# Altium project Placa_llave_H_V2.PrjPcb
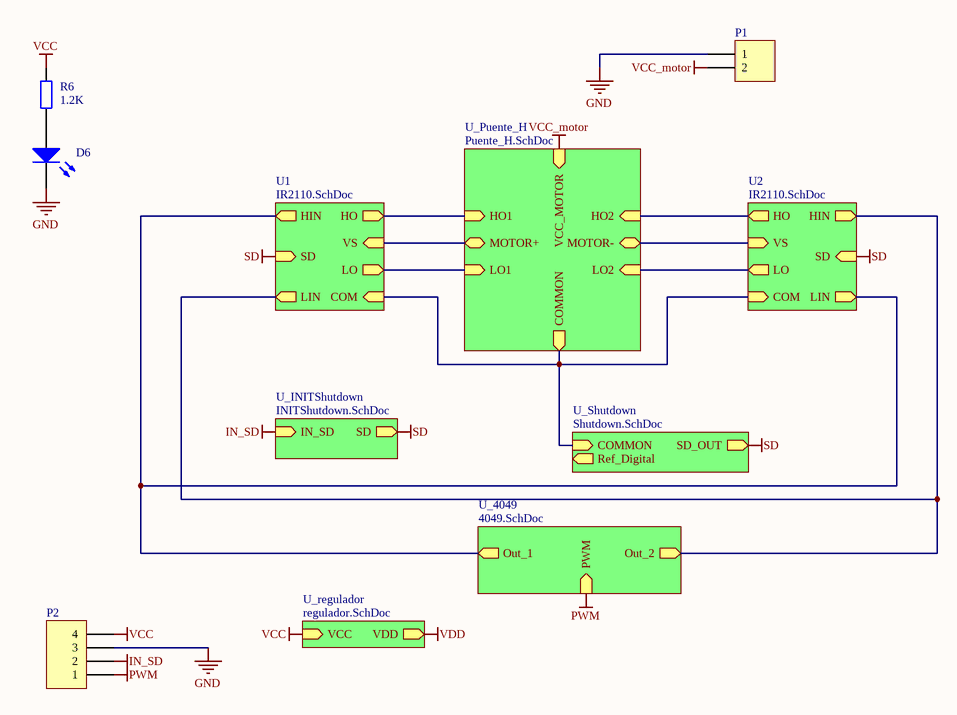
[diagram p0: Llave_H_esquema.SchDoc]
8 sheets, 113 parts. Net scope: hierarchical (ports join the sheet entries above them; power ports are global).
Board file: PCB_llave_H_version_2.PcbDoc
Sheets:
  Llave_H_esquema.SchDoc
    U1 = IR2110.SchDoc
    U2 = IR2110.SchDoc
    U_Puente_H = Puente_H.SchDoc
    U_INITShutdown = INITShutdown.SchDoc
    U_Shutdown = Shutdown.SchDoc
    U_4049 = 4049.SchDoc
    U_regulador = regulador.SchDoc
  ESQUEMA_GRAL.SchDoc

## Sheet Llave_H_esquema.SchDoc
size A4

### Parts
(Parts that share a designator on the sheet are numbered #1, #2 ... from top to bottom, then left to right.)
D6#1  LED0  [CAPPR2.5-6.3X5]  (value not drawn)
P1#1  Header 2  [pwheader1x2]  (value not drawn)
P2#1  Header 4  [HDR1X5]  (value not drawn)
R6#1  1.2k  [AXIAL-0.3]

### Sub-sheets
U1 = IR2110.SchDoc: SD (in), HIN (out), LIN (out), HO (out), LO (out), VS (in), COM (in)
U2 = IR2110.SchDoc: SD (in), HIN (out), LIN (out), HO (out), LO (out), VS (in), COM (in)
U_4049 = 4049.SchDoc: PWM (in), Out_1 (out), Out_2 (out)
U_INITShutdown = INITShutdown.SchDoc: IN_SD (in), SD (out)
U_Puente_H = Puente_H.SchDoc: HO1 (in), LO1 (in), HO2 (in), LO2 (in), MOTOR+ (bidir), MOTOR- (bidir), VCC_MOTOR (in), COMMON (out)
U_regulador = regulador.SchDoc: VCC (in), VDD (out)
U_Shutdown = Shutdown.SchDoc: COMMON (in), SD_OUT (out), Ref_Digital (out)

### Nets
COM: sheet U1/COM, sheet U2/COM, sheet U_Puente_H/COMMON, sheet U_Shutdown/COMMON
GND: D6#1.2(K) P1#1.1 P2#1.3
HIN: sheet U1/HIN, sheet U1/LIN, sheet U2/HIN, sheet U2/LIN, sheet U_4049/Out_1, sheet U_4049/Out_2
HO: sheet U1/HO, sheet U2/HO, sheet U_Puente_H/HO1, sheet U_Puente_H/HO2
IN_SD: P2#1.2 ; sheet U_INITShutdown/IN_SD
LO: sheet U1/LO, sheet U2/LO, sheet U_Puente_H/LO1, sheet U_Puente_H/LO2
MOTOR+: sheet U1/VS, sheet U_Puente_H/MOTOR+
MOTOR-: sheet U2/VS, sheet U_Puente_H/MOTOR-
PWM: P2#1.1 ; sheet U_4049/PWM
SD: sheet U1/SD, sheet U2/SD, sheet U_INITShutdown/SD, sheet U_Shutdown/SD_OUT
VCC: P2#1.4 R6#1.2 ; sheet U_regulador/VCC
VCC_motor: P1#1.2 ; sheet U_Puente_H/VCC_MOTOR
NetD6#1_1: D6#1.1(A) R6#1.1

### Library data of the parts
D6#1 = LED0: Typical INFRARED GaAs LED
P1#1 = Header 2: Header, 2-Pin; value: pw1x2
P2#1 = Header 4: Header, 4-Pin; value: hdr1x5
R6#1 = Res2: Resistor

## Sheet IR2110.SchDoc
size A4
Used 2 times, as channels U1, U2. Parts and nets are listed once, with the designators drawn on the sheet.
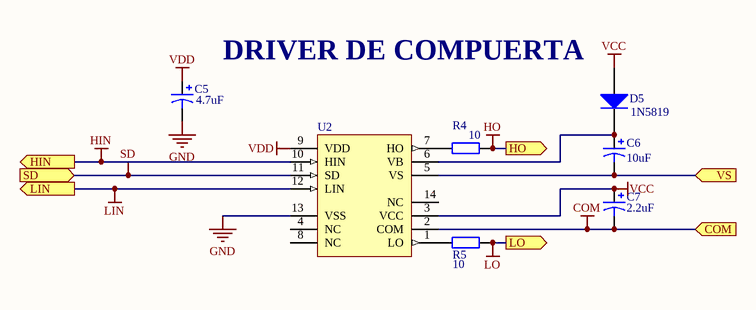
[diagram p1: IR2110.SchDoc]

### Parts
C5  value 4.7uF  [CAPPR2.5-6.3X5]  (hidden comment: Cap Pol1 4.7u)
C6  value 10uF  [CAPPR2.5-6.3X5]  (hidden comment: Cap Pol1)
C7  value 2.2uF  [CAPPR2.5-6.3X5]  (hidden comment: Cap Pol1)
D5  value 1N5819  [DO-204AL]  (hidden comment: Diode)
R4  10  [AXIAL-0.3]
R5  10  [AXIAL-0.3]
U2  IR2110  [PDIP14]  (value not drawn)

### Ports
COM (in), HIN (out), HO (out), LIN (out), LO (out), SD (in), VS (in)

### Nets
COM: C7.2 U2.2(COM) ; port COM
GND: C5.2 U2.13(VSS)
HIN: U2.10(HIN) ; port HIN
HO: R4.2 ; port HO
LIN: U2.12(LIN) ; port LIN
LO: R5.2 ; port LO
SD: U2.11(SD) ; port SD
VCC: C7.1 D5.1(A) U2.3(VCC)
VDD: C5.1 U2.9(VDD)
VS: C6.2 U2.5(VS) ; port VS
NetC6_1: C6.1 D5.2(K) U2.6(VB)
NetR4_1: R4.1 U2.7(HO)
NetR5_1: R5.1 U2.1(LO)

Not connected (* = marked no-connect by the designer): U2 4(NC) 8(NC) 14(NC)

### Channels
U1: designators C5=U1.C5 C6=U1.C6 C7=U1.C7 D5=U1.D5 R4=U1.R4 R5=U1.R5 U2=U1.U2; ports COM=COM HIN=HIN HO=HO LIN=HIN LO=LO SD=SD VS=MOTOR+
U2: designators C5=U2.C5 C6=U2.C6 C7=U2.C7 D5=U2.D5 R4=U2.R4 R5=U2.R5 U2=U2.U2; ports COM=COM HIN=HIN HO=HO LIN=HIN LO=LO SD=SD VS=MOTOR-

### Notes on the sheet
- (near C5) DRIVER DE COMPUERTA

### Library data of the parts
C5-C7 = Cap Pol1: Polarized Capacitor (Radial)
D5 = Diode: 1N5819
R4 R5 = Res2: Resistor
U2 = IR2110: High and Low Side Driver; Note: Pins 4, 8 and 14 are not connected

## Sheet Puente_H.SchDoc
size A4
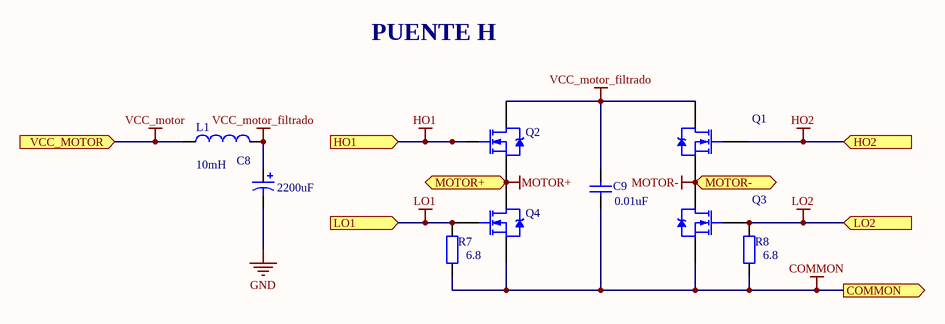
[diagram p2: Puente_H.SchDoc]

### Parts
(Parts that share a designator on the sheet are numbered #1, #2 ... from top to bottom, then left to right.)
C8#1  value 2200uF  [CAPPR5-13X16]  (hidden comment: Cap Pol1)
C9#1  value 0.01uF  [RAD-0.2]  (hidden comment: Cap)
L1#1  value 10mH  [bobina_Choque]  (hidden comment: Inductor)
Q1#1  IRF3205  [To_220_H]  (value not drawn)
Q2#1  IRF3205  [To_220_H]  (value not drawn)
Q3#1  IRF3205  [To_220_H]  (value not drawn)
Q4#1  IRF3205  [To_220_H]  (value not drawn)
R7#1  6.8  [AXIAL-0.3]
R8#1  6.8  [AXIAL-0.3]

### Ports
COMMON (out), HO1 (in), HO2 (in), LO1 (in), LO2 (in), MOTOR+ (bidir), MOTOR- (bidir), VCC_MOTOR (in)

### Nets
COMMON: C9#1.1 Q3#1.3(S) Q4#1.3(S) R7#1.1 R8#1.1 ; port COMMON  [project net COM]
GND: C8#1.2
HO1: Q1#1.1(G) Q2#1.1(G) ; port HO1, port HO2  [also labelled HO2]  [project net HO]
LO1: Q3#1.1(G) Q4#1.1(G) R7#1.2 R8#1.2 ; port LO1, port LO2  [also labelled LO2]  [project net LO]
MOTOR+: Q2#1.3(S) Q4#1.2(D) ; port MOTOR+
MOTOR-: Q1#1.3(S) Q3#1.2(D) ; port MOTOR-
VCC_motor: L1#1.1 ; port VCC_MOTOR
VCC_motor_filtrado: C8#1.1 C9#1.2 L1#1.2 Q1#1.2(D) Q2#1.2(D)

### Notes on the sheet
- PUENTE H

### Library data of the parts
C8#1 = Cap Pol1: Polarized Capacitor (Radial)
C9#1 = Cap: Capacitor
L1#1 = Inductor: Code_IEC: 1005
Q1#1 Q2#1 Q3#1 Q4#1 = IRF3205: HEXFET Power MOSFET; Note: Pin 2 is electrically connected to pin 4.
R7#1 R8#1 = Res2: Resistor

## Sheet INITShutdown.SchDoc
size A4
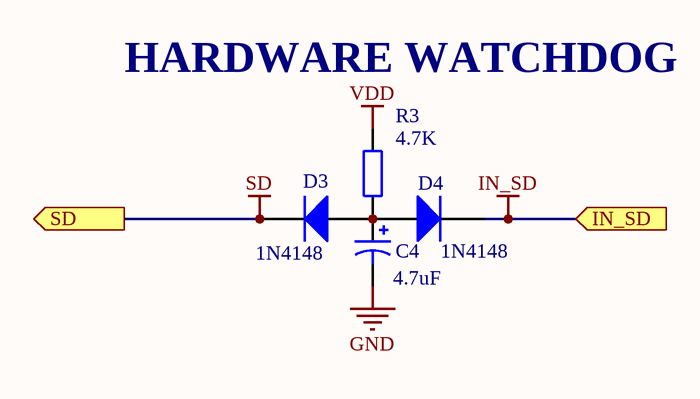
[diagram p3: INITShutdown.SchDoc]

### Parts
(Parts that share a designator on the sheet are numbered #1, #2 ... from top to bottom, then left to right.)
C4#1  value 4.7uF  [CAPPR2.5-6.3X5]  (hidden comment: Cap Pol1 4.7u)
D3#1  value 1N4148  [DO-35]  (hidden comment: Diode1)
D4#1  value 1N4148  [DO-35]  (hidden comment: Diode1)
R3#1  4.7k  [AXIAL-0.3]

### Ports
IN_SD (in), SD (out)

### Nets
GND: C4#1.2
IN_SD: D4#1.2(K) ; port IN_SD
SD: D3#1.2(K) ; port SD
VDD: R3#1.2
NetC4#1_1: C4#1.1 D3#1.1(A) D4#1.1(A) R3#1.1

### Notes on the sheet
- (near R3#1) HARDWARE WATCHDOG

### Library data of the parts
C4#1 = Cap Pol1: Polarized Capacitor (Radial)
D3#1 D4#1 = Diode: 1N4148
R3#1 = Res2: Resistor

## Sheet Shutdown.SchDoc
size A4
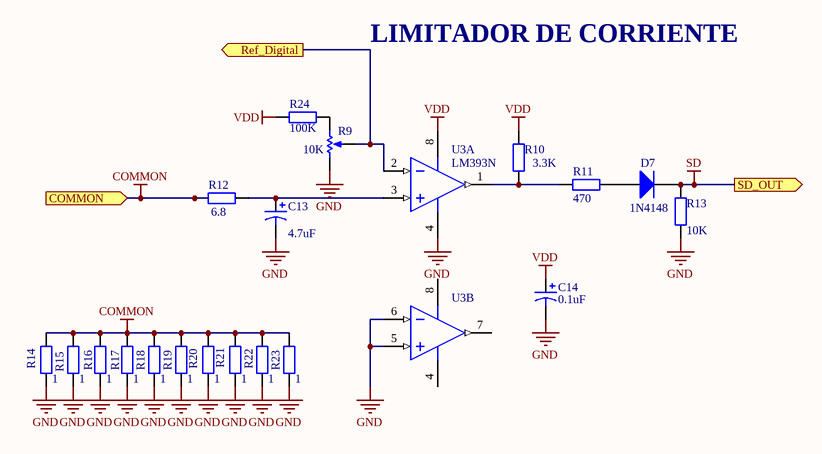
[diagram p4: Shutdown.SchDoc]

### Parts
(Parts that share a designator on the sheet are numbered #1, #2 ... from top to bottom, then left to right.)
C13#1  value 4.7uF  [CAPPR2.5-6.3X5]  (hidden comment: Cap Pol1 4.7u)
C14#1  value 0.1uF  [CAPPR2.5-6.3X5]  (hidden comment: Cap Pol1 0.1u)
D7#1  value 1N4148  [DO-35]  (hidden comment: Diode1)
R9#1  value 10K  [VR5]  (hidden comment: RPot)
R10#1  3.3k  [AXIAL-0.3]
R11#1  470  [AXIAL-0.3]
R12#1  6.8  [AXIAL-0.3]
R13#1  10k  [AXIAL-0.3]
R14#1  value 1  [AXIAL-0.4]  (hidden comment: Res2)
R15#1  value 1  [AXIAL-0.4]  (hidden comment: Res2)
R16#1  value 1  [AXIAL-0.4]  (hidden comment: Res2)
R17#1  value 1  [AXIAL-0.4]  (hidden comment: Res2)
R18#1  value 1  [AXIAL-0.4]  (hidden comment: Res2)
R19#1  value 1  [AXIAL-0.4]  (hidden comment: Res2)
R20#1  value 1  [AXIAL-0.4]  (hidden comment: Res2)
R21#1  value 1  [AXIAL-0.4]  (hidden comment: Res2)
R22#1  value 1  [AXIAL-0.4]  (hidden comment: Res2)
R23#1  value 1  [AXIAL-0.4]  (hidden comment: Res2)
R24  value 100K  [AXIAL-0.3]  (hidden comment: 6.8)
U3#1  LM393N  [626-05]  (parts A,B of 2)

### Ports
COMMON (in), Ref_Digital (out), SD_OUT (out)

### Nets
COMMON: R12#1.1 R14#1.2 R15#1.2 R16#1.2 R17#1.2 R18#1.2 R19#1.2 R20#1.2 R21#1.2 R22#1.2 R23#1.2 ; port COMMON  [project net COM]
GND: C13#1.2 C14#1.2 R9#1.1(TOP) R13#1.1 R14#1.1 R15#1.1 R16#1.1 R17#1.1 R18#1.1 R19#1.1 R20#1.1 R21#1.1 R22#1.1 R23#1.1 U3#1.4(GND) U3#1.5(IN+) U3#1.6(IN-)
SD: D7#1.2(K) R13#1.2 ; port SD_OUT
VDD: C14#1.1 R10#1.2 R24.2 U3#1.8(V+)
NetC13#1_1: C13#1.1 R12#1.2 U3#1.3(IN+)
NetD7#1_1: D7#1.1(A) R11#1.2
NetR9#1_2: R9#1.2(BOT) R24.1
NetR9#1_3: R9#1.3(TAP) U3#1.2(IN-) ; port Ref_Digital
NetR10#1_1: R10#1.1 R11#1.1 U3#1.1(OUT)

Not connected (* = marked no-connect by the designer): U3#1 7(OUT)

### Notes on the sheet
- LIMITADOR DE CORRIENTE

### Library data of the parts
C13#1 = Cap Pol1: Polarized 16V
C14#1 = Cap Pol1: Polarized Capacitor (Radial)
D7#1 = Diode: 1N4148
R9#1 = RPot: Potenciomentro multivuelta; Sim Note: Enter the Resistance value and the set point into parameter fields.; Set Position: 0.5
R10#1 R11#1 R12#1 R13#1 R24 = Res2: Resistor
R14#1 R15#1 R16#1 R17#1 R18#1 R19#1 R20#1 R21#1 R22#1 R23#1 = Res2: metal film 1W
U3#1 = LM393N: Dual Comparator

## Sheet 4049.SchDoc
size A4
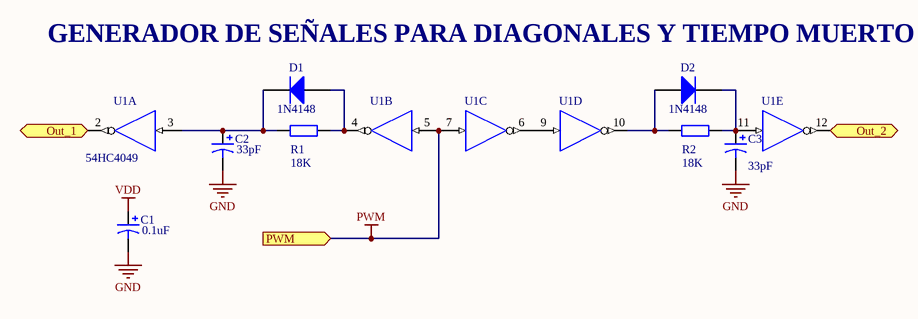
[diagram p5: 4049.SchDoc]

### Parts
(Parts that share a designator on the sheet are numbered #1, #2 ... from top to bottom, then left to right.)
C1#1  value 0.1uF  [CAPPR2.5-6.3X5]  (hidden comment: Cap Pol1 0.1u)
C2#1  value 33pF  [CAPPR2.5-6.3X5]  (hidden comment: Cap Pol1)
C3#1  value 33pF  [CAPPR2.5-6.3X5]  (hidden comment: Cap Pol1)
D1#1  value 1N4148  [DO-35]  (hidden comment: Diode1)
D2#1  value 1N4148  [DO-35]  (hidden comment: Diode1)
R1#1  18k  [AXIAL-0.3]
R2#1  18k  [AXIAL-0.3]
U1#1  value 54HC4049  [620-09]  (hidden comment: MC54HC4049J)  (parts A,B,C,D,E of 6)

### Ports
Out_1 (out), Out_2 (out), PWM (in)

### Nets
GND: C1#1.2 C2#1.2 C3#1.2 U1#1.8(GND)
HIN: U1#1.2(Y) U1#1.12(Y) ; port Out_1, port Out_2
PWM: U1#1.5(A) U1#1.7(A) ; port PWM
VDD: C1#1.1 U1#1.1(VDD)
NetC2#1_1: C2#1.1 D1#1.2(K) R1#1.1 U1#1.3(A)
NetC3#1_1: C3#1.1 D2#1.2(K) R2#1.2 U1#1.11(A)
NetD1#1_1: D1#1.1(A) R1#1.2 U1#1.4(Y)
NetD2#1_1: D2#1.1(A) R2#1.1 U1#1.10(Y)
NetU1#1_6: U1#1.6(Y) U1#1.9(A)

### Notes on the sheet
- GENERADOR DE SEÑALES PARA DIAGONALES Y TIEMPO MUERTO

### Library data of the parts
C1#1 C2#1 C3#1 = Cap Pol1: Polarized Capacitor (Radial)
D1#1 D2#1 = Diode: 1N4148
R1#1 R2#1 = Res2: Resistor
U1#1 = MC54HC4049J: Hex Inverting Buffer/Logic-Level Down Converter; Note: Pins 13 & 16 are NC and not drawn.

## Sheet regulador.SchDoc
size A4
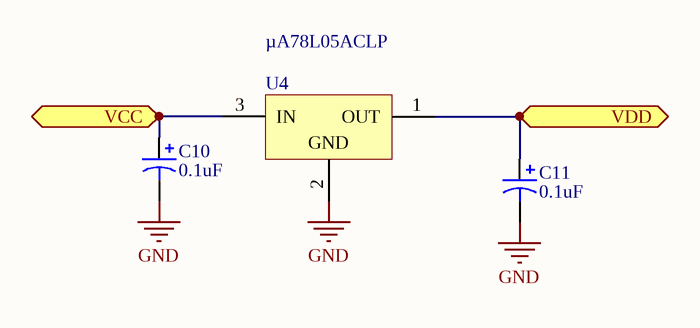
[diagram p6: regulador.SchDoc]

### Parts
C10  value 0.1uF  [CAPPR2.5-6.3X5]  (hidden comment: Cap Pol1 0.1u)
C11  value 0.1uF  [CAPPR2.5-6.3X5]  (hidden comment: Cap Pol1 0.1u)
U4  µA78L05ACLP  [LP03]

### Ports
VCC (in), VDD (out)

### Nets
GND: C10.2 C11.2 U4.2(GND)
VCC: C10.1 U4.3(IN) ; port VCC
VDD: C11.1 U4.1(OUT) ; port VDD

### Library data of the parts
C10 C11 = Cap Pol1: Polarized Capacitor (Radial)
U4 = µA78L05ACLP: Positive-Voltage Regulator

## Sheet ESQUEMA_GRAL.SchDoc
size A3; PageSetup: Record=PageOptions|CenterHorizontal=True|CenterVertical=True|PrintScale=0.71|XCorrection=1.00|YCorrection=1.00|PrintKind=1|BorderSize=5000000|LeftOffset=0|BottomOffset=0|Orientation=2|PaperLength=1000|PaperWidth=1000|Scale=100|PaperSource=15|PrintQuality=1200|MediaType=1|DitherType=10|PaperKind=A4|PrintScaleMode=1
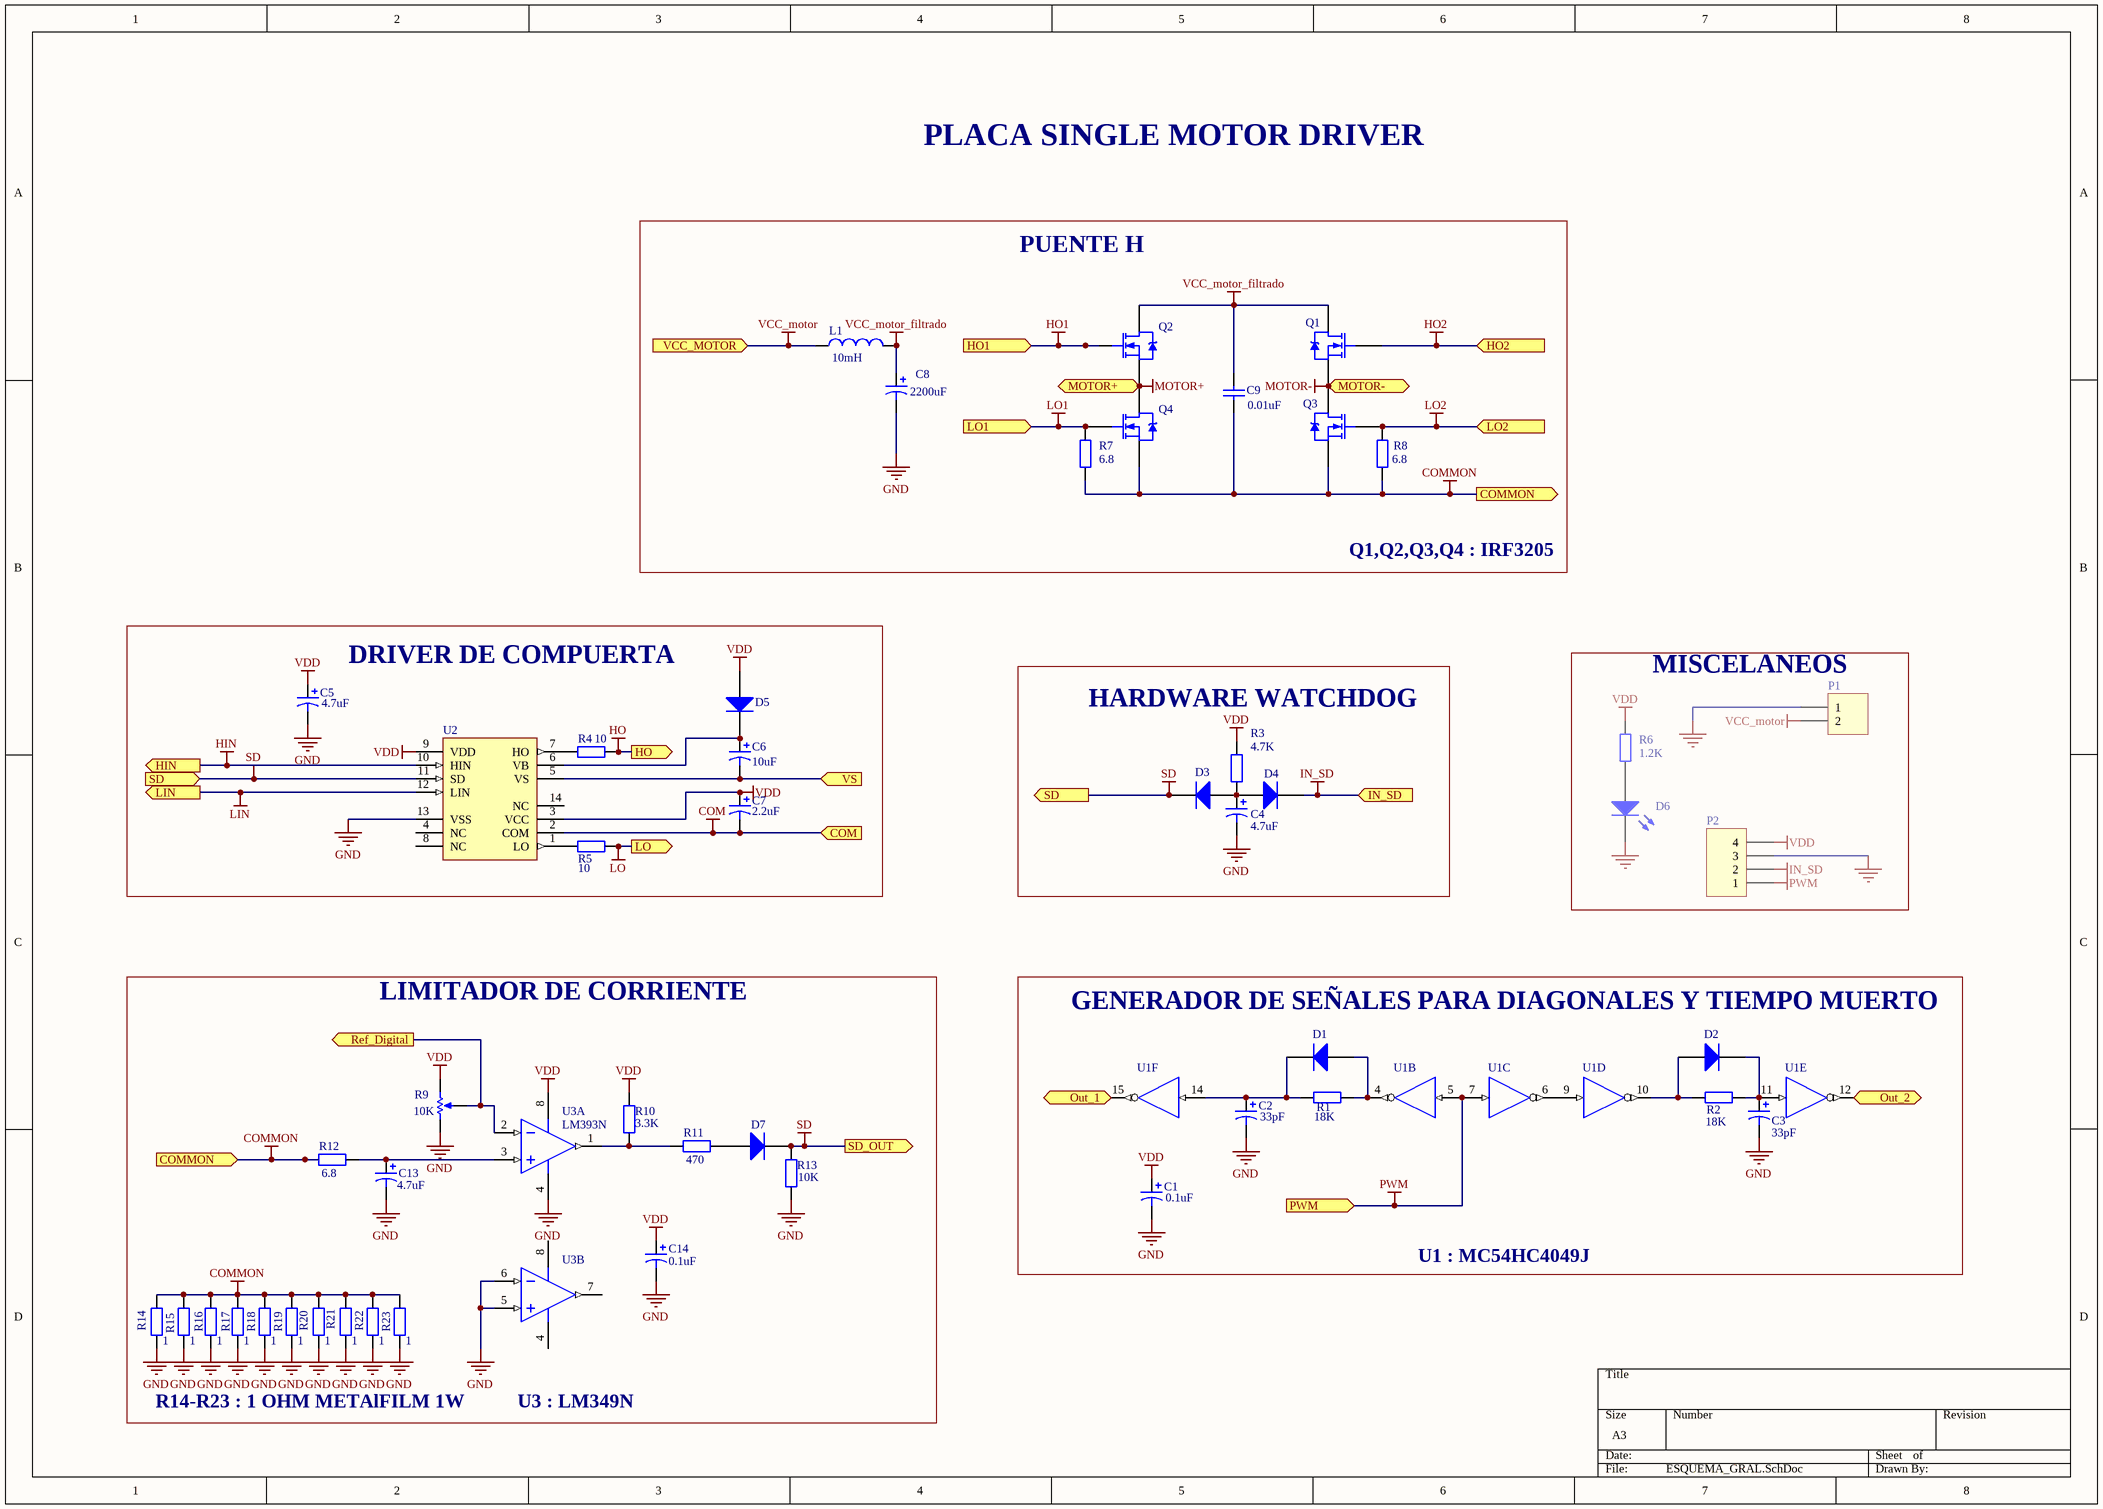
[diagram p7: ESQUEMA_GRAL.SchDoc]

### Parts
(Parts that share a designator on the sheet are numbered #1, #2 ... from top to bottom, then left to right.)
C1#2  value 0.1uF  [CAPPR2.5-6.3X5]  (hidden comment: Cap Pol1)
C2#2  value 33pF  [CAPPR2.5-6.3X5]  (hidden comment: Cap Pol1)
C3#2  value 33pF  [CAPPR2.5-6.3X5]  (hidden comment: Cap Pol1)
C4#2  value 4.7uF  [CAPPR2.5-6.3X5]  (hidden comment: Cap Pol1)
C5  value 4.7uF  [CAPPR2.5-6.3X5]  (hidden comment: Cap Pol1)
C6  value 10uF  [CAPPR2.5-6.3X5]  (hidden comment: Cap Pol1)
C7  value 2.2uF  [CAPPR2.5-6.3X5]  (hidden comment: Cap Pol1)
C8#2  value 2200uF  [CAPPR5-13X16]  (hidden comment: Cap Pol1)
C9#2  value 0.01uF  [RAD-0.2]  (hidden comment: Cap)
C13#2  value 4.7uF  [CAPPR2.5-6.3X5]  (hidden comment: Cap Pol1)
C14#2  value 0.1uF  [CAPPR2.5-6.3X5]  (hidden comment: Cap Pol1)
D1#2  Diode  [DO-35]  (value not drawn)
D2#2  Diode  [DO-35]  (value not drawn)
D3#2  Diode  [DO-204AL]  (value not drawn)
D4#2  Diode  [DO-204AL]  (value not drawn)
D5  Diode  [DO-204AL]  (value not drawn)
D6#2  LED0  [CAPPR2.5-6.3X5]  (value not drawn)
D7#2  Diode  [DO-204AL]  (value not drawn)
L1#2  value 10mH  [bobina_Choque]  (hidden comment: Inductor)
P1#2  Header 2  [pwheader1x2]  (value not drawn)
P2#2  Header 4  [HDR1X5]  (value not drawn)
Q1#2  IRF3205  [TO-220AB]  (value not drawn)
Q2#2  IRF3205  [TO-220AB]  (value not drawn)
Q3#2  IRF3205  [TO-220AB]  (value not drawn)
Q4#2  IRF3205  [TO-220AB]  (value not drawn)
R1#2  value 18K  [AXIAL-0.3]  (hidden comment: Res2)
R2#2  value 18K  [AXIAL-0.3]  (hidden comment: Res2)
R3#2  value 4.7K  [AXIAL-0.3]  (hidden comment: Res2)
R4  value 10  [AXIAL-0.3]  (hidden comment: Res2)
R5  value 10  [AXIAL-0.3]  (hidden comment: Res2)
R6#2  value 1.2K  [AXIAL-0.3]  (hidden comment: Res2)
R7#2  value 6.8  [AXIAL-0.3]  (hidden comment: Res2)
R8#2  value 6.8  [AXIAL-0.3]  (hidden comment: Res2)
R9#2  value 10K  [VR5]  (hidden comment: RPot)
R10#2  value 3.3K  [AXIAL-0.3]  (hidden comment: Res2)
R11#2  value 470  [AXIAL-0.3]  (hidden comment: Res2)
R12#2  value 6.8  [AXIAL-0.3]  (hidden comment: Res2)
R13#2  value 10K  [AXIAL-0.3]  (hidden comment: Res2)
R14#2  value 1  [AXIAL-0.4]  (hidden comment: Res2)
R15#2  value 1  [AXIAL-0.4]  (hidden comment: Res2)
R16#2  value 1  [AXIAL-0.4]  (hidden comment: Res2)
R17#2  value 1  [AXIAL-0.4]  (hidden comment: Res2)
R18#2  value 1  [AXIAL-0.4]  (hidden comment: Res2)
R19#2  value 1  [AXIAL-0.4]  (hidden comment: Res2)
R20#2  value 1  [AXIAL-0.4]  (hidden comment: Res2)
R21#2  value 1  [AXIAL-0.4]  (hidden comment: Res2)
R22#2  value 1  [AXIAL-0.4]  (hidden comment: Res2)
R23#2  value 1  [AXIAL-0.4]  (hidden comment: Res2)
U1#1  MC54HC4049J  [620-09]  (value not drawn)  (part F of 6)
U1#2  MC54HC4049J  [620-09]  (value not drawn)  (parts B,C,D,E of 6)
U2  IR2110  [PDIP14]  (value not drawn)
U3#2  LM393N  [626-05]  (parts A,B of 2)

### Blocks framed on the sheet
PUENTE H: C8#2 C9#2 L1#2 Q1#2 Q2#2 Q3#2 Q4#2 R7#2 R8#2
DRIVER DE COMPUERTA: C5-C7 D5 R4 R5 U2
HARDWARE WATCHDOG: C4#2 D3#2 D4#2 R3#2
MISCELANEOS: D6#2 P1#2 P2#2 R6#2
LIMITADOR DE CORRIENTE: C13#2 C14#2 D7#2 R9#2 R10#2 R11#2 R12#2 R13#2 R14#2 R15#2 R16#2 R17#2 R18#2 R19#2 R20#2 R21#2 R22#2 R23#2 U3#2
GENERADOR DE SEÑALES PARA DIAGONALES Y TIEMPO MUERTO: C1#2 C2#2 C3#2 D1#2 D2#2 R1#2 R2#2 U1#1 U1#2

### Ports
COM (in), COMMON (in), COMMON (out), HIN (out), HO1 (in), HO2 (in), HO (out), IN_SD (in), LIN (out), LO1 (in), LO2 (in), LO (out), MOTOR+ (bidir), MOTOR- (bidir), Out_1 (out), Out_2 (out), PWM (in), Ref_Digital (out), SD (in), SD (out), SD_OUT (out), VCC_MOTOR (in), VS (in)

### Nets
COM: C7.2 C9#2.1 Q3#2.3(S) Q4#2.3(S) R7#2.1 R8#2.1 R12#2.1 R14#2.2 R15#2.2 R16#2.2 R17#2.2 R18#2.2 R19#2.2 R20#2.2 R21#2.2 R22#2.2 R23#2.2 U2.2(COM) ; port COMMON, port COM  [also labelled COMMON]
GND: C1#2.2 C2#2.2 C3#2.2 C4#2.2 C5.2 C8#2.2 C13#2.2 C14#2.2 D6#2.2(K) P1#2.1 P2#2.3 R9#2.1(TOP) R13#2.1 R14#2.1 R15#2.1 R16#2.1 R17#2.1 R18#2.1 R19#2.1 R20#2.1 R21#2.1 R22#2.1 R23#2.1 U1#1.8(GND) U1#2.8(GND) U2.13(VSS) U3#2.4(GND) U3#2.5(IN+) U3#2.6(IN-)
HIN: U2.10(HIN) U2.12(LIN) ; port HIN, port LIN  [also labelled LIN]
HO: Q1#2.1(G) Q2#2.1(G) R4.2 ; port HO1, port HO2, port HO  [also labelled HO1, HO2]
IN_SD: D4#2.2(K) P2#2.2 ; port IN_SD
LO: Q3#2.1(G) Q4#2.1(G) R5.2 R7#2.2 R8#2.2 ; port LO1, port LO2, port LO  [also labelled LO1, LO2]
MOTOR+: Q2#2.3(S) Q4#2.2(D) ; port MOTOR+
MOTOR-: Q1#2.3(S) Q3#2.2(D) ; port MOTOR-
PWM: P2#2.1 U1#2.5(A) U1#2.7(A) ; port PWM
SD: D3#2.2(K) D7#2.2(K) R13#2.2 U2.11(SD) ; port SD_OUT, port SD
VCC_motor: L1#2.1 P1#2.2 ; port VCC_MOTOR
VCC_motor_filtrado: C8#2.1 C9#2.2 L1#2.2 Q1#2.2(D) Q2#2.2(D)
VDD: C1#2.1 C5.1 C7.1 C14#2.1 D5.1(A) P2#2.4 R3#2.2 R6#2.2 R9#2.2(BOT) R10#2.2 U1#1.1(VDD) U1#2.1(VDD) U2.3(VCC) U2.9(VDD) U3#2.8(V+)
NetC2#2_1: C2#2.1 D1#2.2(K) R1#2.1 U1#1.14(A)
NetC3#2_1: C3#2.1 D2#2.2(K) R2#2.2 U1#2.11(A)
NetC4#2_1: C4#2.1 D3#2.1(A) D4#2.1(A) R3#2.1
NetC6_1: C6.1 D5.2(K) U2.6(VB)
NetC6_2: C6.2 U2.5(VS) ; port VS
NetC13#2_1: C13#2.1 R12#2.2 U3#2.3(IN+)
NetD1#2_1: D1#2.1(A) R1#2.2 U1#2.4(Y)
NetD2#2_1: D2#2.1(A) R2#2.1 U1#2.10(Y)
NetD6#2_1: D6#2.1(A) R6#2.1
NetD7#2_1: D7#2.1(A) R11#2.2
NetR4_1: R4.1 U2.7(HO)
NetR5_1: R5.1 U2.1(LO)
NetR9#2_3: R9#2.3(TAP) U3#2.2(IN-) ; port Ref_Digital
NetR10#2_1: R10#2.1 R11#2.1 U3#2.1(OUT)
NetU1#1_15: U1#1.15(Y) ; port Out_1
NetU1#2_6: U1#2.6(Y) U1#2.9(A)
NetU1#2_12: U1#2.12(Y) ; port Out_2

Not connected (* = marked no-connect by the designer): U2 4(NC) 8(NC) 14(NC); U3#2 7(OUT)

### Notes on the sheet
- PLACA SINGLE MOTOR DRIVER
- Q1,Q2,Q3,Q4 : IRF3205
- U1 : MC54HC4049J
- R14-R23 : 1 OHM METAlFILM 1W
- U3 : LM349N

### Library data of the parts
C1#2 C2#2 C3#2 C4#2 C5-C7 C8#2 C14#2 = Cap Pol1: Polarized Capacitor (Radial)
C9#2 = Cap: Capacitor
C13#2 = Cap Pol1: Polarized 16V
D1#2 D2#2 = Diode: 1N4148
D3#2 D4#2 D7#2 = Diode: 1n4148
D5 = Diode: 1N5819
D6#2 = LED0: Typical INFRARED GaAs LED
L1#2 = Inductor: Code_IEC: 1005
P1#2 = Header 2: Header, 2-Pin
P2#2 = Header 4: Header, 4-Pin
Q1#2 Q2#2 Q3#2 Q4#2 = IRF3205: as Q1#1 on sheet Puente_H
R1#2 R2#2 R3#2 R4 R5 R6#2 R7#2 R8#2 = Res2: Resistor
R9#2 = RPot: as R9#1 on sheet Shutdown
R10#2 R11#2 R12#2 R13#2 = Res2: metal film 1/2 W
R14#2 R15#2 R16#2 R17#2 R18#2 R19#2 R20#2 R21#2 R22#2 R23#2 = Res2: metal film 1W
U1#1 U1#2 = MC54HC4049J: as U1#1 on sheet 4049
U2 = IR2110: as U2 on sheet IR2110
U3#2 = LM393N: Dual Comparator

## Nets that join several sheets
COM: U1 (U1.C7.2 U1.U2.2), U2 (U2.C7.2 U2.U2.2), Puente_H (5 pins), Shutdown (11 pins), ESQUEMA_GRAL (18 pins)
GND: Llave_H_esquema (D6#1.2 P1#1.1 P2#1.3), U1 (U1.C5.2 U1.U2.13), U2 (U2.C5.2 U2.U2.13), Puente_H (C8#1.2), INITShutdown (C4#1.2), Shutdown (17 pins), 4049 (C1#1.2 C2#1.2 C3#1.2 U1#1.8), regulador (C10.2 C11.2 U4.2), ESQUEMA_GRAL (29 pins)
HIN: U1 (U1.U2.10 U1.U2.12), U2 (U2.U2.10 U2.U2.12), 4049 (U1#1.2 U1#1.12), ESQUEMA_GRAL (U2.10 U2.12)
HO: U1 (U1.R4.2), U2 (U2.R4.2), Puente_H (Q1#1.1 Q2#1.1), ESQUEMA_GRAL (Q1#2.1 Q2#2.1 R4.2)
IN_SD: Llave_H_esquema (P2#1.2), INITShutdown (D4#1.2), ESQUEMA_GRAL (D4#2.2 P2#2.2)
LO: U1 (U1.R5.2), U2 (U2.R5.2), Puente_H (Q3#1.1 Q4#1.1 R7#1.2 R8#1.2), ESQUEMA_GRAL (5 pins)
MOTOR+: U1 (U1.C6.2 U1.U2.5), Puente_H (Q2#1.3 Q4#1.2), ESQUEMA_GRAL (Q2#2.3 Q4#2.2)
MOTOR-: U2 (U2.C6.2 U2.U2.5), Puente_H (Q1#1.3 Q3#1.2), ESQUEMA_GRAL (Q1#2.3 Q3#2.2)
PWM: Llave_H_esquema (P2#1.1), 4049 (U1#1.5 U1#1.7), ESQUEMA_GRAL (P2#2.1 U1#2.5 U1#2.7)
SD: U1 (U1.U2.11), U2 (U2.U2.11), INITShutdown (D3#1.2), Shutdown (D7#1.2 R13#1.2), ESQUEMA_GRAL (D3#2.2 D7#2.2 R13#2.2 U2.11)
VCC: Llave_H_esquema (P2#1.4 R6#1.2), U1 (U1.C7.1 U1.D5.1 U1.U2.3), U2 (U2.C7.1 U2.D5.1 U2.U2.3), regulador (C10.1 U4.3)
VCC_motor: Llave_H_esquema (P1#1.2), Puente_H (L1#1.1), ESQUEMA_GRAL (L1#2.1 P1#2.2)
VCC_motor_filtrado: Puente_H (5 pins), ESQUEMA_GRAL (5 pins)
VDD: U1 (U1.C5.1 U1.U2.9), U2 (U2.C5.1 U2.U2.9), INITShutdown (R3#1.2), Shutdown (C14#1.1 R10#1.2 R24.2 U3#1.8), 4049 (C1#1.1 U1#1.1), regulador (C11.1 U4.1), ESQUEMA_GRAL (15 pins)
